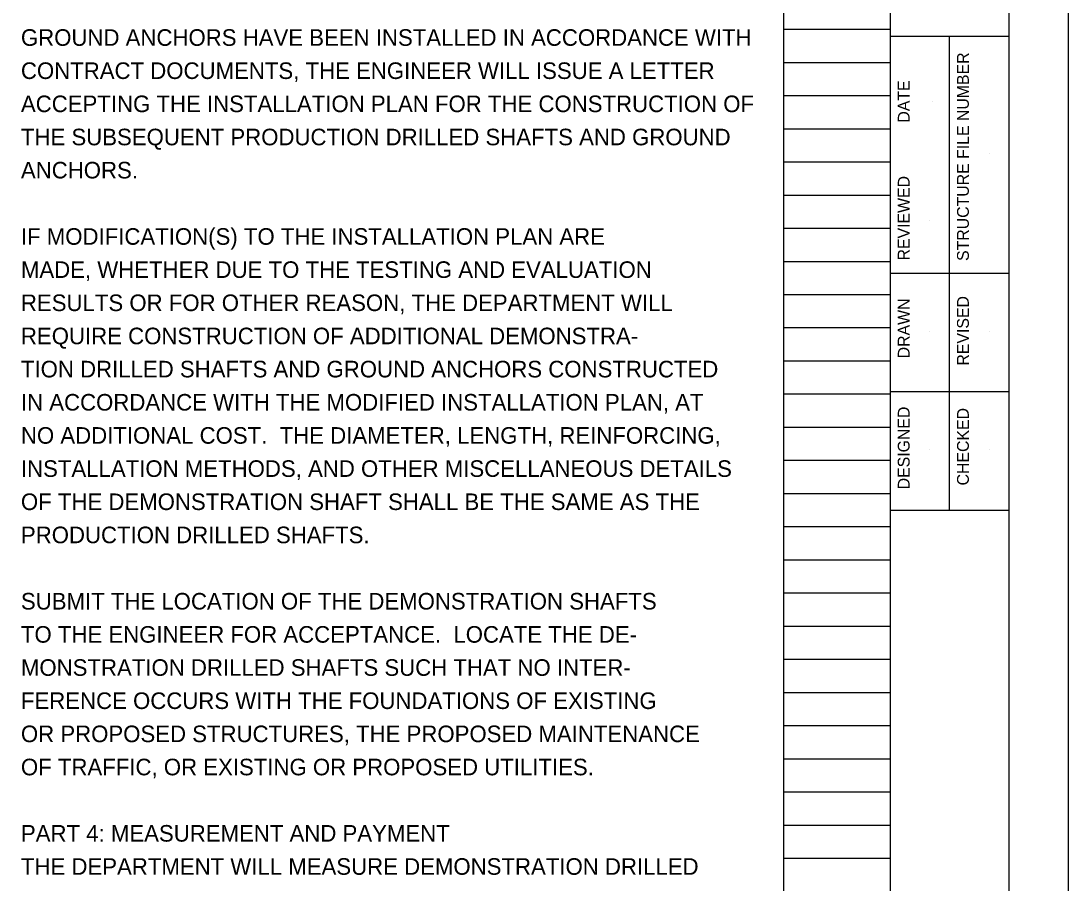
# Model space of a CAD drawing. Extents: x -0.2 to 33.8, y -0.1 to 21.9.
# Drawn here: x 24.94 to 33.78, y 10.72 to 18 of the extents above; entities that cross this region are included whole.
import ezdxf

# ---------------------------------------------------------------- set-up
doc = ezdxf.new("R2010")
doc.units = 0
for name, color, linetype in [('SH_Border', 7, 'Continuous'), ('SH_Cut_Line', 7, 'Continuous'), ('SH_Data', 7, 'Continuous'), ('SH_Text', 7, 'Continuous')]:
    doc.layers.add(name, color=color, linetype=linetype)

msp = doc.modelspace()

# ---------------------------------------------------------------- linework, layer by layer
at = {"layer": 'SH_Border'}
for p, q in [((32.2753, 0.368), (32.2753, 21.368)), ((32.2753, 17.8681), (33.2753, 17.8681)), ((32.7753, 13.8681), (32.7753, 17.8681)), ((32.2753, 15.8681), (33.2753, 15.8681)), ((32.2753, 14.8681), (33.2753, 14.8681)), ((32.2753, 13.8681), (33.2753, 13.8681))]:
    msp.add_line(p, q, dxfattribs=at)
msp.add_lwpolyline([(1.7753, 21.368), (33.2753, 21.368), (33.2753, 0.368), (1.7753, 0.368)], close=True, dxfattribs=at)
at = {"layer": 'SH_Cut_Line'}
msp.add_lwpolyline([(-0.2247, 21.868), (33.7753, 21.868), (33.7753, -0.132), (-0.2247, -0.132)], close=True, dxfattribs=at)
at = {"layer": 'SH_Data'}
for p, q in [((31.3753, 0.848), (31.3753, 21.008)), ((32.2753, 0.848), (32.2753, 21.008)), ((31.3753, 17.928), (32.2753, 17.928)), ((31.3753, 17.648), (32.2753, 17.648)), ((31.3753, 17.368), (32.2753, 17.368)), ((32.6349, 17.3173), (32.6349, 17.3173)), ((31.3753, 17.088), (32.2753, 17.088)), ((31.3753, 16.808), (32.2753, 16.808)), ((33.1086, 16.877), (33.1086, 16.877)), ((31.3753, 16.528), (32.2753, 16.528)), ((32.6086, 16.3154), (32.6086, 16.3154)), ((31.3753, 16.248), (32.2753, 16.248)), ((31.3753, 15.968), (32.2753, 15.968)), ((31.3753, 15.688), (32.2753, 15.688)), ((31.3753, 15.408), (32.2753, 15.408)), ((32.6086, 15.3779), (32.6086, 15.3779)), ((33.1086, 15.3779), (33.1086, 15.3779)), ((31.3753, 15.128), (32.2753, 15.128)), ((31.3753, 14.848), (32.2753, 14.848)), ((31.3753, 14.568), (32.2753, 14.568)), ((32.6086, 14.3779), (32.6086, 14.3779)), ((33.1086, 14.377), (33.1086, 14.377)), ((31.3753, 14.288), (32.2753, 14.288)), ((31.3753, 14.008), (32.2753, 14.008)), ((31.3753, 13.728), (32.2753, 13.728)), ((31.3753, 13.448), (32.2753, 13.448)), ((31.3753, 13.168), (32.2753, 13.168)), ((31.3753, 12.888), (32.2753, 12.888)), ((31.3753, 12.608), (32.2753, 12.608)), ((31.3753, 12.328), (32.2753, 12.328)), ((31.3753, 12.048), (32.2753, 12.048)), ((31.3753, 11.768), (32.2753, 11.768)), ((31.3753, 11.488), (32.2753, 11.488)), ((31.3753, 11.208), (32.2753, 11.208)), ((31.3753, 10.928), (32.2753, 10.928))]:
    msp.add_line(p, q, dxfattribs=at)

# ---------------------------------------------------------------- texts
for s, p in [('STRUCTURE FILE NUMBER', (32.9378, 15.9713)), ('DATE', (32.4378, 17.1395)), ('REVIEWED', (32.4378, 15.9756)), ('REVISED', (32.9378, 15.0878)), ('DRAWN', (32.4378, 15.1492)), ('DESIGNED', (32.4378, 14.0429)), ('CHECKED', (32.9378, 14.0759))]:
    msp.add_text(s, height=0.1, rotation=90, dxfattribs=at).set_placement(p)
at = {"layer": 'SH_Text'}
for s, p in [('GROUND ANCHORS HAVE BEEN INSTALLED IN ACCORDANCE WITH ', (24.9353, 17.788)), ('CONTRACT DOCUMENTS, THE ENGINEER WILL ISSUE A LETTER ', (24.9353, 17.508)), ('ACCEPTING THE INSTALLATION PLAN FOR THE CONSTRUCTION OF ', (24.9353, 17.228)), ('THE SUBSEQUENT PRODUCTION DRILLED SHAFTS AND GROUND ', (24.9353, 16.948)), ('ANCHORS.', (24.9353, 16.668)), ('IF MODIFICATION(S) TO THE INSTALLATION PLAN ARE', (24.9353, 16.108)), ('MADE, WHETHER DUE TO THE TESTING AND EVALUATION', (24.9353, 15.828)), ('RESULTS OR FOR OTHER REASON, THE DEPARTMENT WILL', (24.9353, 15.548)), ('REQUIRE CONSTRUCTION OF ADDITIONAL DEMONSTRA-', (24.9353, 15.268)), ('TION DRILLED SHAFTS AND GROUND ANCHORS CONSTRUCTED', (24.9353, 14.988)), ('IN ACCORDANCE WITH THE MODIFIED INSTALLATION PLAN, AT ', (24.9353, 14.708)), ('NO ADDITIONAL COST.  THE DIAMETER, LENGTH, REINFORCING, ', (24.9353, 14.428)), ('INSTALLATION METHODS, AND OTHER MISCELLANEOUS DETAILS', (24.9353, 14.148)), ('OF THE DEMONSTRATION SHAFT SHALL BE THE SAME AS THE ', (24.9353, 13.868)), ('PRODUCTION DRILLED SHAFTS.', (24.9353, 13.588)), ('SUBMIT THE LOCATION OF THE DEMONSTRATION SHAFTS', (24.9353, 13.028)), ('TO THE ENGINEER FOR ACCEPTANCE.  LOCATE THE DE-', (24.9353, 12.748)), ('MONSTRATION DRILLED SHAFTS SUCH THAT NO INTER-', (24.9353, 12.468)), ('FERENCE OCCURS WITH THE FOUNDATIONS OF EXISTING', (24.9353, 12.188)), ('OR PROPOSED STRUCTURES, THE PROPOSED MAINTENANCE', (24.9353, 11.908)), ('OF TRAFFIC, OR EXISTING OR PROPOSED UTILITIES.', (24.9353, 11.628)), ('PART 4: MEASUREMENT AND PAYMENT', (24.9353, 11.068)), ('THE DEPARTMENT WILL MEASURE DEMONSTRATION DRILLED', (24.9353, 10.788))]:
    msp.add_text(s, height=0.14, dxfattribs=at).set_placement(p)

doc.saveas('drawing.dxf')
